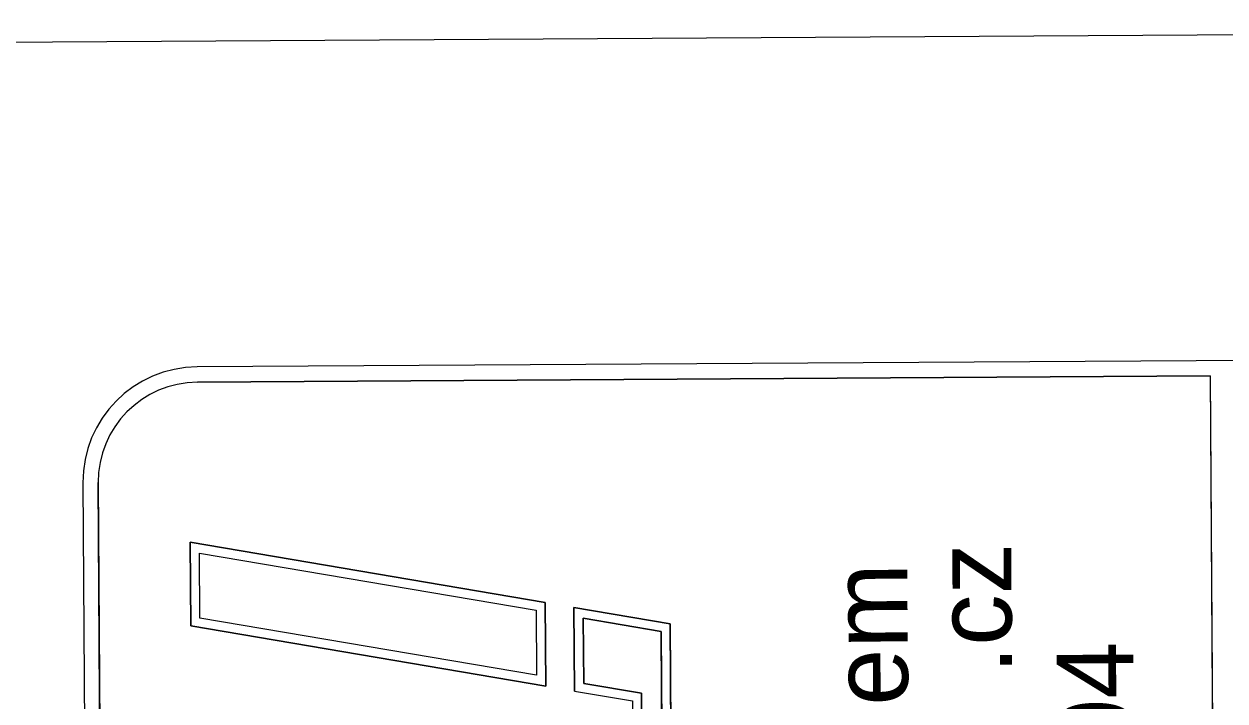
# Model space of a CAD drawing. Extents: x -735036 to -734743, y -1144813 to -1144181.
# Drawn here: x -734820.65 to -734790.92, y -1144197.41 to -1144180.65 of the extents above; entities that cross this region are included whole.
import ezdxf

# ---------------------------------------------------------------- set-up
doc = ezdxf.new("R2010")
doc.units = 0
doc.layers.add('000_rozpiska', color=7, linetype='Continuous')

# ---------------------------------------------------------------- blocks, each defined once
blk = doc.blocks.new('A$C2B726605')
at = {"layer": '000_rozpiska'}
for p, q in [((-8.894, 71.716), (-181.794, 71.716)), ((-8.894, 71.716), (-181.794, 71.716)), ((-8.894, 71.336), (-63.044, 71.336)), ((-14.003, 60.287), (-12.456, 69.067)), ((-12.456, 69.067), (-10.382, 69.067)), ((-10.382, 69.067), (-11.929, 60.287)), ((-13.731, 60.515), (-12.264, 68.839)), ((-12.264, 68.839), (-10.654, 68.839)), ((-10.654, 68.839), (-12.121, 60.515)), ((-6.424, 43.784), (-6.424, 68.866)), ((-6.044, 8.894), (-6.044, 68.866)), ((-6.044, 8.894), (-6.044, 68.866)), ((-12.121, 60.515), (-13.731, 60.515)), ((-11.929, 60.287), (-14.003, 60.287)), ((-14.128, 59.574), (-14.38, 58.143)), ((-14.128, 59.574), (-12.055, 59.574)), ((-12.055, 59.574), (-12.474, 57.193)), ((-13.937, 59.346), (-14.189, 57.915)), ((-13.937, 59.346), (-12.326, 59.346)), ((-12.326, 59.346), (-12.666, 57.421)), ((-14.38, 58.143), (-23.004, 58.143)), ((-14.189, 57.915), (-22.812, 57.915)), ((-12.666, 57.421), (-22.899, 57.421)), ((-12.474, 57.193), (-23.171, 57.193)), ((-6.424, 43.784), (-63.044, 43.784))]:
    blk.add_line(p, q, dxfattribs=at)
for points in [[(-63.044, 43.784), (-63.044, 71.336), (-8.894, 71.336)], [(-10.382, 69.067), (-12.456, 69.067), (-14.003, 60.287), (-11.929, 60.287), (-10.382, 69.067)], [(-6.424, 68.866), (-6.424, 43.784), (-63.044, 43.784)], [(-10.654, 68.839), (-12.121, 60.515), (-13.731, 60.515), (-12.264, 68.839), (-10.654, 68.839)], [(-12.055, 59.574), (-14.128, 59.574), (-14.38, 58.143), (-23.004, 58.143), (-23.171, 57.193), (-12.474, 57.193), (-12.055, 59.574)], [(-12.326, 59.346), (-12.666, 57.421), (-22.899, 57.421), (-22.812, 57.915), (-14.189, 57.915), (-13.937, 59.346), (-12.326, 59.346)], [(-12.326, 59.346), (-13.937, 59.346), (-14.189, 57.915), (-22.812, 57.915), (-22.899, 57.421), (-12.666, 57.421), (-12.326, 59.346)]]:
    blk.add_lwpolyline(points, dxfattribs=at)
for radius, start in [(2.85, 0), (2.85, 360), (2.47, 0), (2.47, 360)]:
    blk.add_arc((-8.894, 68.866), radius, start, 90, dxfattribs=at)
for s, p in [('Labem', (-18.775, 51.316)), ('.cz', (-13.774, 48.739)), ('Tel: 411 198 004', (-32.058, 45.729))]:
    blk.add_text(s, height=1.9, dxfattribs=at).set_placement(p)

msp = doc.modelspace()

# ---------------------------------------------------------------- linework, layer by layer
at = {"layer": '000_rozpiska'}
msp.add_line((-734746.942, -1144180.653), (-735035.936, -1144182.44), dxfattribs=at)

# ---------------------------------------------------------------- block references
at = {"layer": '000_rozpiska', "rotation": 90.35414249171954}
msp.add_blockref('A$C2B726605', (-734747.538, -1144182.67), dxfattribs=at)

doc.saveas('drawing.dxf')
